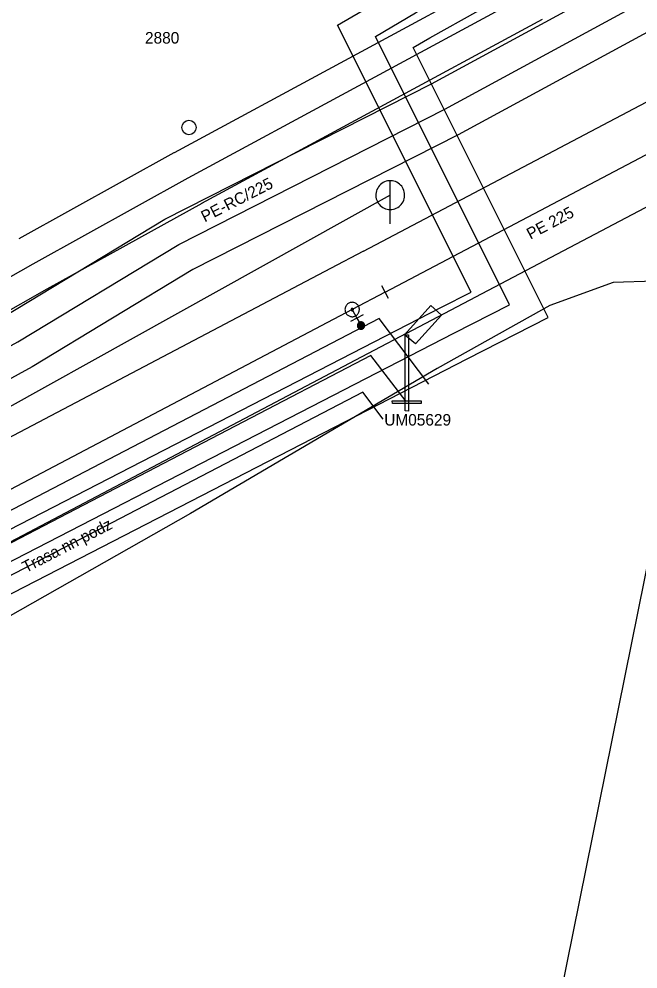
# Model space of a CAD drawing. Extents: x -762993 to -761845, y -975230 to -974501.
# Drawn here: x -762340.27 to -762318.78, y -975055.68 to -975022.72 of the extents above; entities that cross this region are included whole.
import ezdxf

# ---------------------------------------------------------------- set-up
doc = ezdxf.new("R2010")
doc.units = 0
for name, color, linetype in [('IS_CETIN_podzem out of order', 7, 'Continuous'), ('IS_CEZ-D_anotace', 7, 'Continuous'), ('IS_CEZ-D_el vedeni NN podzem', 7, 'Continuous'), ('IS_CEZ-D_OP', 7, 'Continuous'), ('IS_CEZ-T_parovod OP', 7, 'Continuous'), ('IS_DPmUL_OP', 7, 'Continuous'), ('IS_DPmUL_trakce anotace', 7, 'Continuous'), ('IS_DPmUL_trakce stozary', 7, 'Continuous'), ('IS_DPmUL_VO lampy', 7, 'Continuous'), ('IS_DPmUL_VO lampy anotace', 7, 'Continuous'), ('IS_DPmUL_VO vedeni podzem', 7, 'Continuous'), ('IS_GASNET_plyn NTL anotace', 7, 'Continuous'), ('IS_GASNET_plyn NTL rad', 7, 'Continuous'), ('IS_GASNET_plyn OP', 7, 'Continuous'), ('IS_SCVK_kanalizace jednotna', 7, 'Continuous'), ('IS_SCVK_kanalizace znaky', 7, 'Continuous'), ('IS_SCVK_vodovod anotace', 7, 'Continuous'), ('IS_SCVK_vodovod OP', 7, 'Continuous'), ('IS_SCVK_vodovod privadec', 7, 'Continuous'), ('IS_SCVK_vodovod znaky', 7, 'Continuous'), ('IS_T-Mobile_OP', 7, 'Continuous'), ('IS_T-Mobile_podzem optika', 7, 'Continuous')]:
    doc.layers.add(name, color=color, linetype=linetype)

msp = doc.modelspace()

# ---------------------------------------------------------------- linework, layer by layer
at = {"layer": 'IS_CETIN_podzem out of order'}
msp.add_lwpolyline([(-762316.97, -975032.44), (-762318.2, -975031.82), (-762319.64, -975031.86), (-762321.84, -975032.66), (-762325.75, -975034.84), (-762334.32, -975039.88), (-762342.38, -975044.44), (-762350.45, -975049.19)], dxfattribs=at)
at = {"layer": 'IS_CEZ-D_el vedeni NN podzem'}
for points in [[(-762323.24, -975032.631), (-762327.897, -975023.324), (-762326.508, -975022.51), (-762316.256, -975016.781), (-762313.888, -975015.684), (-762313.128, -975014.455), (-762313.114, -975014.417), (-762312.341, -975012.334), (-762312.311, -975012.253), (-762312.434, -975011.429)], [(-762344.041, -975050.919), (-762343.85, -975050.809), (-762344.384, -975050.4), (-762344.485, -975050.24), (-762347.642, -975045.187), (-762325.172, -975033.619), (-762323.24, -975032.631)]]:
    msp.add_lwpolyline(points, dxfattribs=at)
at = {"layer": 'IS_CEZ-D_OP'}
for points in [[(-762321.902, -975033.07), (-762326.584, -975023.714), (-762326.011, -975023.378), (-762315.801, -975017.672), (-762313.195, -975016.465), (-762312.224, -975014.895), (-762312.176, -975014.764), (-762311.559, -975013.102)], [(-762324.578, -975032.192), (-762329.21, -975022.934), (-762327.005, -975021.642), (-762319.049, -975017.196)], [(-762348.912, -975045.041), (-762349.066, -975044.795), (-762325.629, -975032.729), (-762324.578, -975032.192)], [(-762343.174, -975051.574), (-762342.051, -975050.927), (-762343.634, -975049.715), (-762343.638, -975049.708), (-762346.218, -975045.579), (-762324.715, -975034.509), (-762321.902, -975033.07)]]:
    msp.add_lwpolyline(points, dxfattribs=at)
at = {"layer": 'IS_CEZ-T_parovod OP'}
msp.add_lwpolyline([(-762321.7, -975057.755), (-762316.3, -975031.029), (-762304.176, -975033.091), (-762303.135, -975025.276)], dxfattribs=at)
at = {"layer": 'IS_DPmUL_OP'}
for points in [[(-762326.04, -975035.386), (-762327.769, -975033.116), (-762356.785, -975048.211)], [(-762327.63, -975036.598), (-762328.339, -975035.668), (-762355.863, -975049.985)]]:
    msp.add_lwpolyline(points, dxfattribs=at)
at = {"layer": 'IS_DPmUL_trakce stozary'}
msp.add_circle((-762334.368, -975026.483), 0.25, dxfattribs=at)
at = {"layer": 'IS_DPmUL_VO lampy'}
for points in [[(-762325.975, -975032.662), (-762325.605, -975032.992), (-762326.505, -975033.992), (-762326.885, -975033.672)], [(-762326.865, -975033.672), (-762326.745, -975033.682), (-762326.745, -975036.322), (-762326.865, -975036.312)], [(-762327.315, -975035.972), (-762326.315, -975035.972), (-762326.315, -975036.062), (-762327.305, -975036.062)]]:
    msp.add_lwpolyline(points, close=True, dxfattribs=at)
at = {"layer": 'IS_DPmUL_VO vedeni podzem'}
msp.add_lwpolyline([(-762326.835, -975035.992), (-762328.054, -975034.392), (-762356.324, -975049.098)], dxfattribs=at)
at = {"layer": 'IS_GASNET_plyn NTL rad'}
msp.add_lwpolyline([(-762382.14, -975056.56), (-762374.12, -975052.41), (-762369.1, -975049.66), (-762366.32, -975048.11), (-762358.1, -975043.65), (-762340.31, -975033.92), (-762334.72, -975030.54), (-762325.49, -975025.85), (-762316.08, -975020.74), (-762311.6, -975018.18), (-762307.32, -975015.61), (-762304.68, -975013.94), (-762304.65, -975013.71), (-762304.31, -975011.18), (-762303.9, -975006.19), (-762303.47, -974998.11), (-762299.684, -974994.021), (-762299.23, -974993.53)], dxfattribs=at)
at = {"layer": 'IS_GASNET_plyn OP'}
for points in [[(-762382.6, -975055.672), (-762374.59, -975051.527), (-762369.584, -975048.785), (-762366.802, -975047.234), (-762358.578, -975042.772), (-762340.809, -975033.053), (-762335.206, -975029.665), (-762325.955, -975024.965), (-762316.567, -975019.866), (-762312.106, -975017.317), (-762307.845, -975014.759), (-762305.61, -975013.345), (-762305.305, -975011.072), (-762304.898, -975006.122), (-762304.449, -974997.696)], [(-762302.491, -974998.524), (-762302.902, -975006.258), (-762303.315, -975011.288), (-762303.659, -975013.841), (-762303.688, -975014.069), (-762303.717, -975014.29), (-762303.957, -975014.666), (-762304.145, -975014.785), (-762306.795, -975016.461), (-762311.094, -975019.043), (-762315.593, -975021.614), (-762325.025, -975026.735), (-762334.234, -975031.415), (-762339.811, -975034.787), (-762357.622, -975044.528), (-762365.838, -975048.986), (-762368.616, -975050.535), (-762373.65, -975053.293), (-762381.68, -975057.448)]]:
    msp.add_lwpolyline(points, dxfattribs=at)
at = {"layer": 'IS_SCVK_kanalizace jednotna'}
for points in [[(-762327.383, -975028.829), (-762371.896, -975053.576)], [(-762328.704, -975032.799), (-762328.545, -975033.101)], [(-762328.545, -975033.101), (-762328.397, -975033.355)]]:
    msp.add_lwpolyline(points, dxfattribs=at)
at = {"layer": 'IS_SCVK_kanalizace znaky'}
for points in [[(-762326.883, -975028.829), (-762326.886, -975028.775), (-762326.895, -975028.721), (-762326.91, -975028.668), (-762326.93, -975028.617), (-762326.956, -975028.569), (-762326.986, -975028.524), (-762327.023, -975028.482), (-762327.062, -975028.445), (-762327.106, -975028.412), (-762327.154, -975028.385), (-762327.204, -975028.362), (-762327.256, -975028.346), (-762327.31, -975028.334), (-762327.364, -975028.329), (-762327.419, -975028.331), (-762327.473, -975028.338), (-762327.527, -975028.35), (-762327.578, -975028.369), (-762327.627, -975028.393), (-762327.673, -975028.422), (-762327.716, -975028.457), (-762327.755, -975028.495), (-762327.789, -975028.538), (-762327.819, -975028.584), (-762327.843, -975028.633), (-762327.861, -975028.685), (-762327.874, -975028.738), (-762327.881, -975028.792), (-762327.883, -975028.847), (-762327.878, -975028.902), (-762327.867, -975028.955), (-762327.85, -975029.007), (-762327.828, -975029.057), (-762327.801, -975029.105), (-762327.768, -975029.149), (-762327.731, -975029.189), (-762327.689, -975029.225), (-762327.644, -975029.256), (-762327.596, -975029.282), (-762327.545, -975029.302), (-762327.493, -975029.317), (-762327.439, -975029.326), (-762327.383, -975029.329), (-762327.329, -975029.326), (-762327.275, -975029.317), (-762327.223, -975029.302), (-762327.172, -975029.282), (-762327.123, -975029.256), (-762327.078, -975029.225), (-762327.037, -975029.19), (-762326.999, -975029.15), (-762326.966, -975029.106), (-762326.939, -975029.059), (-762326.917, -975029.008), (-762326.9, -975028.957), (-762326.889, -975028.903), (-762326.883, -975028.848), (-762326.883, -975028.829)], [(-762327.383, -975029.829), (-762327.383, -975028.329)]]:
    msp.add_lwpolyline(points, dxfattribs=at)
at = {"layer": 'IS_SCVK_vodovod OP'}
for points in [[(-762328.311, -975030.77), (-762315.298, -975023.919), (-762310.29, -975026.455)], [(-762326.809, -975033.624), (-762315.27, -975027.549), (-762311.748, -975029.333)], [(-762328.311, -975030.77), (-762329.455, -975031.372)], [(-762329.455, -975031.372), (-762359.025, -975046.938), (-762371.27, -975053.725)], [(-762326.809, -975033.624), (-762327.953, -975034.226)], [(-762327.953, -975034.226), (-762357.493, -975049.776), (-762369.706, -975056.545)]]:
    msp.add_lwpolyline(points, dxfattribs=at)
at = {"layer": 'IS_SCVK_vodovod privadec'}
for points in [[(-762327.56, -975032.197), (-762315.284, -975025.734), (-762311.019, -975027.894)], [(-762327.56, -975032.197), (-762328.704, -975032.799)], [(-762328.704, -975032.799), (-762358.259, -975048.357), (-762370.488, -975055.135)]]:
    msp.add_lwpolyline(points, dxfattribs=at)
at = {"layer": 'IS_SCVK_vodovod znaky'}
for points in [[(-762327.443, -975032.418), (-762327.676, -975031.976)], [(-762328.925, -975032.915), (-762328.912, -975032.938), (-762328.896, -975032.959), (-762328.878, -975032.978), (-762328.859, -975032.995), (-762328.837, -975033.01), (-762328.814, -975033.023), (-762328.79, -975033.033), (-762328.765, -975033.041), (-762328.74, -975033.046), (-762328.714, -975033.049), (-762328.687, -975033.048), (-762328.662, -975033.045), (-762328.636, -975033.04), (-762328.611, -975033.031), (-762328.588, -975033.02), (-762328.565, -975033.007), (-762328.544, -975032.991), (-762328.525, -975032.973), (-762328.508, -975032.954), (-762328.493, -975032.932), (-762328.48, -975032.909), (-762328.469, -975032.885), (-762328.462, -975032.86), (-762328.456, -975032.834), (-762328.454, -975032.809), (-762328.454, -975032.782), (-762328.458, -975032.756), (-762328.463, -975032.731), (-762328.471, -975032.706), (-762328.483, -975032.682), (-762328.496, -975032.66), (-762328.512, -975032.639), (-762328.529, -975032.62), (-762328.549, -975032.603), (-762328.571, -975032.588), (-762328.593, -975032.575), (-762328.617, -975032.564), (-762328.642, -975032.556), (-762328.668, -975032.551), (-762328.694, -975032.549), (-762328.721, -975032.55), (-762328.746, -975032.552), (-762328.772, -975032.558), (-762328.797, -975032.567), (-762328.82, -975032.578), (-762328.843, -975032.591), (-762328.864, -975032.606), (-762328.883, -975032.624), (-762328.9, -975032.644), (-762328.915, -975032.666), (-762328.928, -975032.688), (-762328.938, -975032.712), (-762328.946, -975032.737), (-762328.951, -975032.763), (-762328.954, -975032.789), (-762328.953, -975032.816), (-762328.95, -975032.841), (-762328.944, -975032.867), (-762328.936, -975032.892), (-762328.925, -975032.915)], [(-762328.74, -975032.818), (-762328.738, -975032.822), (-762328.735, -975032.825), (-762328.733, -975032.828), (-762328.729, -975032.831), (-762328.726, -975032.834), (-762328.722, -975032.836), (-762328.718, -975032.838), (-762328.714, -975032.839), (-762328.709, -975032.839), (-762328.706, -975032.84), (-762328.701, -975032.84), (-762328.697, -975032.839), (-762328.693, -975032.838), (-762328.689, -975032.837), (-762328.685, -975032.835), (-762328.681, -975032.833), (-762328.677, -975032.83), (-762328.675, -975032.828), (-762328.672, -975032.824), (-762328.669, -975032.821), (-762328.667, -975032.817), (-762328.665, -975032.813), (-762328.664, -975032.809), (-762328.663, -975032.805), (-762328.663, -975032.801), (-762328.663, -975032.796), (-762328.664, -975032.792), (-762328.665, -975032.788), (-762328.666, -975032.784), (-762328.667, -975032.78), (-762328.67, -975032.775), (-762328.672, -975032.773), (-762328.675, -975032.77), (-762328.679, -975032.767), (-762328.682, -975032.764), (-762328.686, -975032.762), (-762328.689, -975032.76), (-762328.694, -975032.759), (-762328.698, -975032.758), (-762328.702, -975032.758), (-762328.707, -975032.758), (-762328.711, -975032.758), (-762328.715, -975032.76), (-762328.719, -975032.761), (-762328.723, -975032.763), (-762328.727, -975032.765), (-762328.73, -975032.768), (-762328.733, -975032.77), (-762328.736, -975032.774), (-762328.739, -975032.777), (-762328.741, -975032.78), (-762328.743, -975032.785), (-762328.743, -975032.789), (-762328.744, -975032.793), (-762328.745, -975032.797), (-762328.745, -975032.802), (-762328.744, -975032.806), (-762328.743, -975032.81), (-762328.742, -975032.814), (-762328.74, -975032.818)], [(-762328.324, -975032.984), (-762328.766, -975033.217)], [(-762328.523, -975033.355), (-762328.523, -975033.368), (-762328.521, -975033.381), (-762328.518, -975033.394), (-762328.513, -975033.406), (-762328.507, -975033.418), (-762328.5, -975033.429), (-762328.492, -975033.439), (-762328.482, -975033.449), (-762328.472, -975033.457), (-762328.461, -975033.464), (-762328.449, -975033.47), (-762328.437, -975033.475), (-762328.424, -975033.478), (-762328.411, -975033.48), (-762328.398, -975033.482), (-762328.385, -975033.481), (-762328.372, -975033.479), (-762328.359, -975033.476), (-762328.347, -975033.471), (-762328.335, -975033.465), (-762328.324, -975033.458), (-762328.314, -975033.45), (-762328.304, -975033.44), (-762328.296, -975033.43), (-762328.289, -975033.419), (-762328.283, -975033.407), (-762328.278, -975033.395), (-762328.275, -975033.382), (-762328.273, -975033.369), (-762328.271, -975033.356), (-762328.272, -975033.343), (-762328.274, -975033.33), (-762328.277, -975033.317), (-762328.282, -975033.305), (-762328.288, -975033.293), (-762328.295, -975033.282), (-762328.303, -975033.272), (-762328.313, -975033.262), (-762328.323, -975033.254), (-762328.334, -975033.247), (-762328.346, -975033.241), (-762328.358, -975033.236), (-762328.371, -975033.233), (-762328.384, -975033.231), (-762328.397, -975033.23), (-762328.41, -975033.23), (-762328.423, -975033.232), (-762328.436, -975033.235), (-762328.448, -975033.24), (-762328.46, -975033.246), (-762328.471, -975033.253), (-762328.481, -975033.261), (-762328.491, -975033.271), (-762328.499, -975033.281), (-762328.506, -975033.292), (-762328.512, -975033.304), (-762328.517, -975033.316), (-762328.52, -975033.329), (-762328.522, -975033.342), (-762328.523, -975033.355)], [(-762328.503, -975033.355), (-762328.504, -975033.366), (-762328.502, -975033.377), (-762328.499, -975033.388), (-762328.495, -975033.398), (-762328.49, -975033.408), (-762328.484, -975033.417), (-762328.477, -975033.426), (-762328.469, -975033.434), (-762328.46, -975033.441), (-762328.451, -975033.447), (-762328.441, -975033.452), (-762328.431, -975033.456), (-762328.42, -975033.459), (-762328.409, -975033.462), (-762328.398, -975033.462), (-762328.387, -975033.462), (-762328.376, -975033.46), (-762328.365, -975033.457), (-762328.355, -975033.453), (-762328.345, -975033.448), (-762328.336, -975033.442), (-762328.327, -975033.435), (-762328.319, -975033.427), (-762328.312, -975033.418), (-762328.306, -975033.409), (-762328.301, -975033.399), (-762328.297, -975033.389), (-762328.294, -975033.378), (-762328.292, -975033.367), (-762328.291, -975033.356), (-762328.291, -975033.345), (-762328.293, -975033.334), (-762328.296, -975033.323), (-762328.3, -975033.313), (-762328.305, -975033.303), (-762328.311, -975033.294), (-762328.318, -975033.285), (-762328.326, -975033.277), (-762328.335, -975033.27), (-762328.344, -975033.264), (-762328.354, -975033.259), (-762328.364, -975033.255), (-762328.375, -975033.252), (-762328.386, -975033.25), (-762328.397, -975033.25), (-762328.408, -975033.249), (-762328.419, -975033.251), (-762328.43, -975033.254), (-762328.44, -975033.258), (-762328.45, -975033.263), (-762328.459, -975033.269), (-762328.468, -975033.276), (-762328.476, -975033.284), (-762328.483, -975033.293), (-762328.489, -975033.302), (-762328.494, -975033.312), (-762328.498, -975033.322), (-762328.501, -975033.333), (-762328.503, -975033.344), (-762328.503, -975033.355)], [(-762328.484, -975033.355), (-762328.484, -975033.364), (-762328.483, -975033.373), (-762328.48, -975033.382), (-762328.477, -975033.39), (-762328.473, -975033.398), (-762328.468, -975033.406), (-762328.462, -975033.413), (-762328.456, -975033.419), (-762328.449, -975033.425), (-762328.441, -975033.43), (-762328.433, -975033.434), (-762328.425, -975033.437), (-762328.416, -975033.44), (-762328.407, -975033.441), (-762328.398, -975033.443), (-762328.389, -975033.442), (-762328.38, -975033.441), (-762328.371, -975033.438), (-762328.363, -975033.435), (-762328.355, -975033.431), (-762328.347, -975033.426), (-762328.34, -975033.42), (-762328.334, -975033.414), (-762328.328, -975033.407), (-762328.323, -975033.399), (-762328.319, -975033.391), (-762328.316, -975033.383), (-762328.313, -975033.374), (-762328.312, -975033.365), (-762328.309, -975033.356), (-762328.311, -975033.347), (-762328.312, -975033.338), (-762328.315, -975033.329), (-762328.318, -975033.321), (-762328.322, -975033.313), (-762328.327, -975033.305), (-762328.333, -975033.298), (-762328.339, -975033.292), (-762328.346, -975033.286), (-762328.354, -975033.281), (-762328.362, -975033.277), (-762328.37, -975033.274), (-762328.379, -975033.271), (-762328.388, -975033.27), (-762328.397, -975033.269), (-762328.406, -975033.269), (-762328.415, -975033.27), (-762328.424, -975033.273), (-762328.432, -975033.276), (-762328.44, -975033.28), (-762328.448, -975033.285), (-762328.455, -975033.291), (-762328.461, -975033.297), (-762328.467, -975033.304), (-762328.472, -975033.312), (-762328.476, -975033.32), (-762328.479, -975033.328), (-762328.482, -975033.337), (-762328.483, -975033.346), (-762328.484, -975033.355)], [(-762328.464, -975033.355), (-762328.464, -975033.362), (-762328.463, -975033.369), (-762328.462, -975033.376), (-762328.459, -975033.382), (-762328.456, -975033.388), (-762328.452, -975033.394), (-762328.448, -975033.4), (-762328.443, -975033.405), (-762328.437, -975033.409), (-762328.431, -975033.413), (-762328.425, -975033.416), (-762328.419, -975033.419), (-762328.412, -975033.42), (-762328.405, -975033.423), (-762328.398, -975033.423), (-762328.391, -975033.423), (-762328.384, -975033.421), (-762328.377, -975033.42), (-762328.371, -975033.417), (-762328.364, -975033.414), (-762328.359, -975033.41), (-762328.353, -975033.406), (-762328.348, -975033.401), (-762328.344, -975033.395), (-762328.34, -975033.389), (-762328.337, -975033.383), (-762328.334, -975033.377), (-762328.332, -975033.37), (-762328.331, -975033.363), (-762328.33, -975033.356), (-762328.33, -975033.349), (-762328.331, -975033.342), (-762328.333, -975033.335), (-762328.336, -975033.329), (-762328.339, -975033.322), (-762328.343, -975033.317), (-762328.347, -975033.311), (-762328.352, -975033.306), (-762328.358, -975033.302), (-762328.363, -975033.298), (-762328.37, -975033.295), (-762328.376, -975033.292), (-762328.383, -975033.29), (-762328.39, -975033.289), (-762328.397, -975033.289), (-762328.404, -975033.289), (-762328.411, -975033.289), (-762328.418, -975033.291), (-762328.424, -975033.294), (-762328.43, -975033.297), (-762328.436, -975033.301), (-762328.442, -975033.305), (-762328.447, -975033.31), (-762328.451, -975033.316), (-762328.455, -975033.321), (-762328.458, -975033.328), (-762328.461, -975033.334), (-762328.462, -975033.341), (-762328.464, -975033.348), (-762328.464, -975033.355)], [(-762328.444, -975033.355), (-762328.444, -975033.36), (-762328.444, -975033.365), (-762328.443, -975033.37), (-762328.441, -975033.374), (-762328.439, -975033.379), (-762328.436, -975033.383), (-762328.433, -975033.386), (-762328.429, -975033.39), (-762328.426, -975033.393), (-762328.422, -975033.396), (-762328.417, -975033.398), (-762328.413, -975033.4), (-762328.408, -975033.401), (-762328.403, -975033.403), (-762328.398, -975033.403), (-762328.393, -975033.403), (-762328.388, -975033.402), (-762328.383, -975033.401), (-762328.379, -975033.399), (-762328.374, -975033.397), (-762328.37, -975033.394), (-762328.366, -975033.391), (-762328.363, -975033.387), (-762328.36, -975033.384), (-762328.357, -975033.38), (-762328.355, -975033.375), (-762328.353, -975033.371), (-762328.352, -975033.366), (-762328.351, -975033.361), (-762328.35, -975033.356), (-762328.35, -975033.351), (-762328.351, -975033.346), (-762328.352, -975033.341), (-762328.354, -975033.337), (-762328.356, -975033.332), (-762328.359, -975033.328), (-762328.362, -975033.324), (-762328.365, -975033.321), (-762328.369, -975033.318), (-762328.373, -975033.315), (-762328.378, -975033.313), (-762328.382, -975033.311), (-762328.387, -975033.31), (-762328.392, -975033.309), (-762328.397, -975033.309), (-762328.402, -975033.309), (-762328.407, -975033.31), (-762328.412, -975033.31), (-762328.416, -975033.312), (-762328.421, -975033.314), (-762328.425, -975033.317), (-762328.428, -975033.32), (-762328.432, -975033.323), (-762328.434, -975033.327), (-762328.438, -975033.331), (-762328.44, -975033.336), (-762328.442, -975033.34), (-762328.443, -975033.345), (-762328.444, -975033.35), (-762328.444, -975033.355)], [(-762328.424, -975033.355), (-762328.424, -975033.358), (-762328.425, -975033.361), (-762328.424, -975033.363), (-762328.423, -975033.366), (-762328.422, -975033.369), (-762328.42, -975033.371), (-762328.418, -975033.373), (-762328.416, -975033.375), (-762328.414, -975033.377), (-762328.412, -975033.379), (-762328.409, -975033.381), (-762328.406, -975033.382), (-762328.404, -975033.382), (-762328.401, -975033.383), (-762328.398, -975033.383), (-762328.395, -975033.383), (-762328.392, -975033.383), (-762328.389, -975033.382), (-762328.387, -975033.381), (-762328.384, -975033.38), (-762328.382, -975033.378), (-762328.379, -975033.376), (-762328.377, -975033.374), (-762328.376, -975033.372), (-762328.374, -975033.37), (-762328.373, -975033.367), (-762328.371, -975033.364), (-762328.371, -975033.362), (-762328.37, -975033.359), (-762328.369, -975033.356), (-762328.37, -975033.353), (-762328.37, -975033.35), (-762328.371, -975033.347), (-762328.372, -975033.345), (-762328.373, -975033.342), (-762328.375, -975033.34), (-762328.376, -975033.337), (-762328.378, -975033.335), (-762328.381, -975033.334), (-762328.383, -975033.332), (-762328.386, -975033.331), (-762328.388, -975033.33), (-762328.391, -975033.329), (-762328.394, -975033.329), (-762328.397, -975033.328), (-762328.4, -975033.329), (-762328.403, -975033.328), (-762328.405, -975033.33), (-762328.408, -975033.33), (-762328.411, -975033.331), (-762328.413, -975033.333), (-762328.415, -975033.334), (-762328.417, -975033.336), (-762328.419, -975033.339), (-762328.421, -975033.341), (-762328.422, -975033.344), (-762328.423, -975033.346), (-762328.424, -975033.349), (-762328.424, -975033.352), (-762328.424, -975033.355)], [(-762328.405, -975033.355), (-762328.405, -975033.357), (-762328.405, -975033.357), (-762328.404, -975033.357), (-762328.404, -975033.359), (-762328.405, -975033.36), (-762328.403, -975033.36), (-762328.403, -975033.36), (-762328.403, -975033.362), (-762328.403, -975033.362), (-762328.402, -975033.363), (-762328.4, -975033.363), (-762328.4, -975033.363), (-762328.4, -975033.364), (-762328.398, -975033.364), (-762328.398, -975033.364), (-762328.397, -975033.364), (-762328.396, -975033.364), (-762328.396, -975033.363), (-762328.395, -975033.363), (-762328.393, -975033.363), (-762328.393, -975033.362), (-762328.393, -975033.362), (-762328.392, -975033.361), (-762328.392, -975033.361), (-762328.39, -975033.36), (-762328.39, -975033.359), (-762328.389, -975033.358), (-762328.389, -975033.358), (-762328.389, -975033.357), (-762328.389, -975033.356), (-762328.389, -975033.355), (-762328.389, -975033.354), (-762328.389, -975033.354), (-762328.39, -975033.353), (-762328.39, -975033.352), (-762328.391, -975033.351), (-762328.391, -975033.351), (-762328.392, -975033.35), (-762328.392, -975033.35), (-762328.393, -975033.349), (-762328.394, -975033.349), (-762328.395, -975033.348), (-762328.395, -975033.348), (-762328.396, -975033.348), (-762328.397, -975033.348), (-762328.398, -975033.348), (-762328.399, -975033.348), (-762328.399, -975033.348), (-762328.4, -975033.349), (-762328.401, -975033.348), (-762328.402, -975033.35), (-762328.402, -975033.35), (-762328.403, -975033.35), (-762328.403, -975033.35), (-762328.404, -975033.352), (-762328.404, -975033.353), (-762328.404, -975033.354), (-762328.405, -975033.354), (-762328.405, -975033.355), (-762328.405, -975033.355)]]:
    msp.add_lwpolyline(points, dxfattribs=at)
at = {"layer": 'IS_T-Mobile_OP'}
for points in [[(-762334.875, -975027.35), (-762323.044, -975020.96)], [(-762333.925, -975029.11), (-762322.094, -975022.72)], [(-762340.265, -975030.335), (-762334.885, -975027.355)], [(-762339.295, -975032.085), (-762333.915, -975029.105)], [(-762342.797, -975034.069), (-762339.287, -975032.08)]]:
    msp.add_lwpolyline(points, dxfattribs=at)
at = {"layer": 'IS_T-Mobile_podzem optika'}
for points in [[(-762334.4, -975028.23), (-762322.569, -975021.84)], [(-762334.4, -975028.23), (-762322.569, -975021.84)], [(-762339.78, -975031.21), (-762334.4, -975028.23)], [(-762339.78, -975031.21), (-762334.4, -975028.23)], [(-762343.29, -975033.199), (-762339.78, -975031.21)], [(-762343.29, -975033.199), (-762339.78, -975031.21)]]:
    msp.add_lwpolyline(points, dxfattribs=at)

# ---------------------------------------------------------------- texts
at = {"layer": 'IS_CEZ-D_anotace'}
msp.add_text('Trasa nn podz', height=0.4, rotation=27.2403, dxfattribs=at).set_placement((-762340.03, -975041.943))
at = {"layer": 'IS_DPmUL_trakce anotace'}
msp.add_text('2880', height=0.4, dxfattribs=at).set_placement((-762335.895, -975023.572))
at = {"layer": 'IS_DPmUL_VO lampy anotace'}
msp.add_text('UM05629', height=0.4, dxfattribs=at).set_placement((-762327.591, -975036.825))
at = {"layer": 'IS_GASNET_plyn NTL anotace'}
msp.add_text('PE-RC/225', height=0.4, rotation=26.9363, dxfattribs=at).set_placement((-762333.822, -975029.782))
at = {"layer": 'IS_SCVK_vodovod anotace'}
msp.add_text('PE 225', height=0.4, rotation=28, dxfattribs=at).set_placement((-762322.516, -975030.382))

doc.saveas('drawing.dxf')
